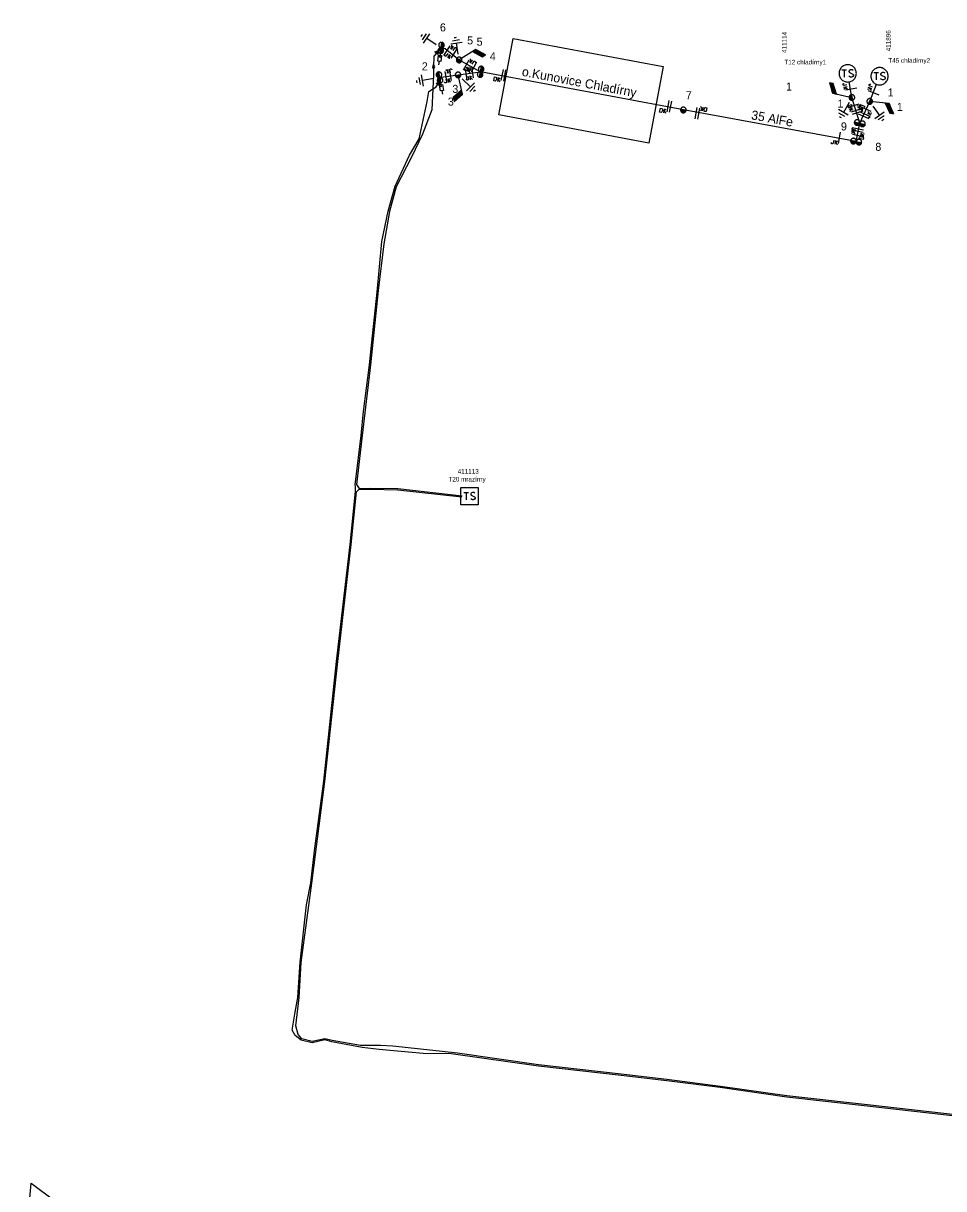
# Model space of a CAD drawing. Extents: x -540340 to -537226, y -1183949 to -1180375.
# Drawn here: x -540340 to -540138.8, y -1183666.6 to -1183411.8 of the extents above; entities that cross this region are included whole.
import ezdxf

# ---------------------------------------------------------------- set-up
doc = ezdxf.new("R2010")
doc.units = 0
for name, color, linetype in [('Default', 7, 'Continuous'), ('Vrstva 11', 7, 'Continuous'), ('Vrstva 12', 7, 'Continuous'), ('Vrstva 13', 7, 'Continuous'), ('Vrstva 14', 7, 'Continuous'), ('Vrstva 15', 7, 'Continuous'), ('Vrstva 16', 7, 'Continuous'), ('Vrstva 18', 7, 'Continuous'), ('Vrstva 19', 7, 'Continuous'), ('Vrstva 2', 7, 'Continuous'), ('Vrstva 25', 7, 'Continuous'), ('Vrstva 26', 7, 'Continuous'), ('Vrstva 27', 7, 'Continuous'), ('Vrstva 35', 7, 'Continuous'), ('Vrstva 4', 7, 'Continuous'), ('Vrstva 5', 7, 'Continuous'), ('Vrstva 52', 7, 'Continuous'), ('Vrstva 53', 7, 'Continuous'), ('Vrstva 54', 7, 'Continuous'), ('Vrstva 6', 7, 'Continuous')]:
    doc.layers.add(name, color=color, linetype=linetype)

# ---------------------------------------------------------------- blocks, each defined once
blk = doc.blocks.new('VN850')
at = {"layer": 'Vrstva 15'}
for points in [[(-0.56, 1.43), (-0.56, -1.07)], [(-0.01, 1.43), (-0.01, -1.07)], [(-2.09, -0.54), (-1.78, -0.54)], [(-2.09, -1.41), (-2.09, -0.54)], [(-1.78, -1.41), (-2.09, -1.41)], [(-1.78, -0.54), (-1.66, -0.6)], [(-1.67, -1.35), (-1.78, -1.41)], [(-1.59, -1.2), (-1.67, -1.35)], [(-1.66, -0.6), (-1.59, -0.75)], [(-1.59, -0.75), (-1.55, -0.96)], [(-1.55, -0.96), (-1.59, -1.2)], [(-1.26, -0.54), (-1.26, -1.41)], [(-0.85, -0.54), (-1.26, -1.09)], [(-1.13, -0.92), (-0.77, -1.41)]]:
    blk.add_lwpolyline(points, dxfattribs=at)
blk = doc.blocks.new('VN840')
at = {"layer": 'Vrstva 15'}
for points in [[(-0.01, 1.41), (-0.01, -1.09)], [(-1.51, -1.24), (-1.51, -1.15)], [(-1.48, -1.35), (-1.51, -1.24)], [(-1.33, -1.42), (-1.48, -1.35)], [(-1.27, -1.42), (-1.33, -1.42)], [(-1.13, -1.35), (-1.27, -1.42)], [(-1.09, -1.24), (-1.13, -1.35)], [(-1.09, -0.59), (-1.09, -1.24)], [(-0.68, -0.59), (-0.68, -1.42)], [(-0.68, -1.11), (-0.27, -0.59)], [(-0.54, -0.94), (-0.2, -1.42)]]:
    blk.add_lwpolyline(points, dxfattribs=at)
blk = doc.blocks.new('VN440')
at = {"layer": 'Vrstva 2'}
for points in [[(1.22, 0), (1.21, 0.13), (1.19, 0.25), (1.16, 0.38), (1.11, 0.5), (1.05, 0.61), (0.98, 0.72), (0.9, 0.82), (0.81, 0.91), (0.71, 0.99), (0.6, 1.06), (0.49, 1.12), (0.37, 1.16), (0.25, 1.2), (0.12, 1.22), (-0.01, 1.22), (-0.14, 1.22), (-0.26, 1.2), (-0.39, 1.16), (-0.51, 1.12), (-0.62, 1.06), (-0.73, 0.99), (-0.83, 0.91), (-0.92, 0.82), (-1, 0.72), (-1.07, 0.61), (-1.13, 0.5), (-1.18, 0.38), (-1.21, 0.25), (-1.23, 0.13), (-1.24, 0), (-1.23, -0.13), (-1.21, -0.26), (-1.18, -0.38), (-1.13, -0.5), (-1.07, -0.62), (-1, -0.73), (-0.92, -0.83), (-0.83, -0.92), (-0.73, -1), (-0.62, -1.07), (-0.51, -1.13), (-0.39, -1.17), (-0.26, -1.2), (-0.14, -1.23), (-0.01, -1.23), (0.12, -1.23), (0.25, -1.2), (0.37, -1.17), (0.49, -1.13), (0.6, -1.07), (0.71, -1), (0.81, -0.92), (0.9, -0.83), (0.98, -0.73), (1.05, -0.62), (1.11, -0.5), (1.16, -0.38), (1.19, -0.26), (1.21, -0.13), (1.22, 0)], [(-1.24, 0), (1.22, 0)], [(-1.18, -0.34), (1.1, -0.34)], [(-1.01, -0.63), (0.97, -0.63)], [(-0.74, -0.92), (0.68, -0.92)]]:
    blk.add_lwpolyline(points, dxfattribs=at)
blk = doc.blocks.new('VN870')
at = {"layer": 'Vrstva 4'}
for points in [[(0, -0.25), (0.5, 0), (0, 0.25), (-0.5, 0), (0, -0.25)], [(0.37, 0), (0, 0.19), (-0.36, 0), (0, -0.19), (0.37, 0)], [(0.24, 0), (0, 0.12), (-0.25, 0), (0, -0.12), (0.24, 0)], [(0.12, 0), (0, 0.06), (-0.13, 0), (0, -0.06), (0.12, 0)]]:
    blk.add_lwpolyline(points, dxfattribs=at)
blk = doc.blocks.new('VN890')
at = {"layer": 'Vrstva 4'}
for points in [[(-0.41, 0.41), (0.41, 0)], [(-0.41, -0.41), (-0.41, 0.41)], [(0.41, 0), (-0.41, -0.41)], [(-0.34, 0.31), (0.27, 0), (-0.34, -0.3), (-0.34, 0.31)], [(-0.26, 0.2), (0.1, 0), (-0.26, -0.18), (-0.26, 0.2)], [(-0.19, 0.09), (-0.04, 0), (-0.19, -0.08), (-0.19, 0.09)], [(-0.16, -0.01), (-0.16, 0.03), (-0.13, 0.01), (-0.16, -0.01)]]:
    blk.add_lwpolyline(points, dxfattribs=at)
blk = doc.blocks.new('VN820')
at = {"layer": 'Vrstva 13'}
for points in [[(0, 0), (0, -2.1)], [(-0.32, -1.63), (0.34, -1.63)], [(-0.32, -2.95), (-0.32, -1.63)], [(0, -2.1), (-0.12, -1.86)], [(0, -2.1), (0.12, -1.86)], [(0.34, -1.63), (0.34, -2.95)], [(0.34, -2.95), (-0.32, -2.95)], [(0, -2.95), (0, -3.75)]]:
    blk.add_lwpolyline(points, dxfattribs=at)
blk = doc.blocks.new('VN810')
at = {"layer": 'Vrstva 14'}
for points in [[(0, -1.25), (0, -3.75)], [(1.25, -3.75), (-1.25, -3.75)], [(0.77, -4.37), (-0.8, -4.37)], [(0, -5), (-0.25, -5)], [(0.27, -5), (0, -5)]]:
    blk.add_lwpolyline(points, dxfattribs=at)
blk = doc.blocks.new('VN640')
at = {"layer": 'Vrstva 6'}
for points in [[(-1.89, 1.89), (1.89, 1.89)], [(-1.89, -1.89), (-1.89, 1.89)], [(-1.26, 0.79), (-0.22, 0.79)], [(-0.73, 0.79), (-0.73, -0.79)], [(1.2, 0.66), (0.94, 0.79), (0.66, 0.79), (0.41, 0.66), (0.28, 0.47), (0.28, 0.41), (0.41, 0.22), (1.13, -0.16), (1.26, -0.32), (1.26, -0.47), (1.13, -0.66), (0.91, -0.79), (0.63, -0.79), (0.5, -0.73), (0.28, -0.6)], [(1.89, 1.89), (1.89, -1.89)], [(1.89, -1.89), (-1.89, -1.89)]]:
    blk.add_lwpolyline(points, dxfattribs=at)
blk = doc.blocks.new('VN610')
at = {"layer": 'Vrstva 6'}
for points in [[(1.88, 0), (1.87, 0.2), (1.84, 0.39), (1.79, 0.58), (1.72, 0.77), (1.63, 0.94), (1.52, 1.11), (1.4, 1.26), (1.26, 1.4), (1.1, 1.53), (0.94, 1.63), (0.76, 1.72), (0.58, 1.8), (0.39, 1.85), (0.19, 1.88), (-0.01, 1.89), (-0.21, 1.88), (-0.4, 1.85), (-0.59, 1.8), (-0.78, 1.72), (-0.95, 1.63), (-1.12, 1.53), (-1.27, 1.4), (-1.41, 1.26), (-1.54, 1.11), (-1.64, 0.94), (-1.73, 0.77), (-1.8, 0.58), (-1.86, 0.39), (-1.89, 0.2), (-1.9, 0), (-1.89, -0.2), (-1.86, -0.39), (-1.8, -0.58), (-1.73, -0.77), (-1.64, -0.95), (-1.54, -1.11), (-1.41, -1.27), (-1.27, -1.41), (-1.12, -1.53), (-0.95, -1.64), (-0.78, -1.73), (-0.59, -1.8), (-0.4, -1.85), (-0.21, -1.88), (-0.01, -1.89), (0.19, -1.88), (0.39, -1.85), (0.58, -1.8), (0.76, -1.73), (0.94, -1.64), (1.1, -1.53), (1.26, -1.41), (1.4, -1.27), (1.52, -1.11), (1.63, -0.95), (1.72, -0.77), (1.79, -0.58), (1.84, -0.39), (1.87, -0.2), (1.88, 0)], [(-1.27, 0.78), (-0.26, 0.78)], [(-0.76, 0.78), (-0.76, -0.79)], [(1.19, 0.66), (0.94, 0.78), (0.62, 0.78), (0.37, 0.66), (0.24, 0.47), (0.24, 0.4), (0.37, 0.22), (1.12, -0.16), (1.25, -0.32), (1.25, -0.48), (1.12, -0.67), (0.87, -0.79), (0.62, -0.79), (0.49, -0.73), (0.24, -0.6)]]:
    blk.add_lwpolyline(points, dxfattribs=at)
blk = doc.blocks.new('VN450')
at = {"layer": 'Vrstva 2'}
for points in [[(0, 0), (-0.01, 0.13), (-0.03, 0.25), (-0.06, 0.38), (-0.11, 0.5), (-0.16, 0.61), (-0.23, 0.72), (-0.31, 0.82), (-0.4, 0.91), (-0.5, 0.99), (-0.61, 1.06), (-0.72, 1.11), (-0.84, 1.16), (-0.97, 1.19), (-1.09, 1.21), (-1.22, 1.22), (-1.35, 1.21), (-1.47, 1.19), (-1.59, 1.16), (-1.71, 1.11), (-1.83, 1.06), (-1.93, 0.99), (-2.03, 0.91), (-2.12, 0.82), (-2.2, 0.72), (-2.27, 0.61), (-2.33, 0.5), (-2.38, 0.38), (-2.41, 0.25), (-2.43, 0.13), (-2.44, 0), (-2.43, -0.13), (-2.41, -0.25), (-2.38, -0.38), (-2.33, -0.5), (-2.27, -0.61), (-2.2, -0.72), (-2.12, -0.82), (-2.03, -0.91), (-1.93, -0.99), (-1.83, -1.06), (-1.71, -1.11), (-1.59, -1.16), (-1.47, -1.19), (-1.35, -1.21), (-1.22, -1.22), (-1.09, -1.21), (-0.97, -1.19), (-0.84, -1.16), (-0.72, -1.11), (-0.61, -1.06), (-0.5, -0.99), (-0.4, -0.91), (-0.31, -0.82), (-0.23, -0.72), (-0.16, -0.61), (-0.11, -0.5), (-0.06, -0.38), (-0.03, -0.25), (-0.01, -0.13), (0, 0)], [(-2.44, 0), (2.44, 0)], [(2.44, 0), (2.43, 0.13), (2.41, 0.25), (2.38, 0.38), (2.33, 0.5), (2.27, 0.61), (2.2, 0.72), (2.12, 0.82), (2.03, 0.91), (1.94, 0.99), (1.83, 1.06), (1.71, 1.11), (1.6, 1.16), (1.47, 1.19), (1.35, 1.21), (1.22, 1.22), (1.09, 1.21), (0.97, 1.19), (0.84, 1.16), (0.72, 1.11), (0.61, 1.06), (0.5, 0.99), (0.4, 0.91), (0.31, 0.82), (0.23, 0.72), (0.16, 0.61), (0.11, 0.5), (0.06, 0.38), (0.03, 0.25), (0.01, 0.13), (0, 0), (0.01, -0.13), (0.03, -0.25), (0.06, -0.38), (0.11, -0.5), (0.16, -0.61), (0.23, -0.72), (0.31, -0.82), (0.4, -0.91), (0.5, -0.99), (0.61, -1.06), (0.72, -1.11), (0.84, -1.16), (0.97, -1.19), (1.09, -1.21), (1.22, -1.22), (1.35, -1.21), (1.47, -1.19), (1.6, -1.16), (1.71, -1.11), (1.83, -1.06), (1.94, -0.99), (2.03, -0.91), (2.12, -0.82), (2.2, -0.72), (2.27, -0.61), (2.33, -0.5), (2.38, -0.38), (2.41, -0.25), (2.43, -0.13), (2.44, 0)], [(-2.4, -0.31), (-0.04, -0.31)], [(-2.26, -0.61), (-0.17, -0.61)], [(-2.01, -0.92), (-0.42, -0.92)], [(0.04, -0.31), (2.4, -0.31)], [(0.17, -0.61), (2.27, -0.61)], [(0.42, -0.92), (2.02, -0.92)]]:
    blk.add_lwpolyline(points, dxfattribs=at)
blk = doc.blocks.new('VN001')
at = {"layer": 'Default'}
for p, q in [((1.73, 3.03), (4.14, 3.03)), ((1.76, 3.08), (4.17, 3.08)), ((1.79, 3.13), (4.2, 3.13)), ((1.82, 3.18), (4.23, 3.18)), ((1.85, 3.23), (4.26, 3.23)), ((1.87, 3.28), (4.29, 3.28)), ((1.9, 3.33), (4.32, 3.33)), ((1.93, 3.38), (4.35, 3.38)), ((1.96, 3.43), (4.37, 3.43)), ((1.99, 3.48), (4.4, 3.48)), ((2.02, 3.53), (4.43, 3.53)), ((2.05, 3.58), (4.46, 3.58)), ((2.07, 3.63), (4.49, 3.63)), ((2.1, 3.68), (4.52, 3.68)), ((2.13, 3.73), (2.54, 3.73))]:
    blk.add_line(p, q, dxfattribs=at)
blk.add_lwpolyline([(2.13, 3.73), (0, 0)], dxfattribs=at)
blk.add_lwpolyline([(4.55, 3.73), (2.13, 3.73), (1.7, 2.98), (4.12, 2.99)], close=True, dxfattribs=at)

msp = doc.modelspace()

# ---------------------------------------------------------------- linework, layer by layer
at = {"layer": 'Vrstva 35'}
for points in [[(-540232.9, -1183415.07), (-540200.11, -1183421.24), (-540203.26, -1183437.95), (-540236.04, -1183431.77)], [(-540099.18, -1183843.5), (-540075.2, -1183846.48), (-540065.47, -1183765.95), (-540052.99, -1183646.29), (-540036.08, -1183648.06), (-540048.58, -1183767.85), (-540059.33, -1183856.85), (-540059.45, -1183876.18), (-540076.45, -1183876.06), (-540087.82, -1183869.73), (-540106.08, -1183859.73), (-540163.52, -1183816.9), (-540239.44, -1183760.31), (-540323.17, -1183697.88), (-540340.03, -1183685.32), (-540338.32, -1183665.38), (-540313.01, -1183684.25), (-540229.28, -1183746.68), (-540153.36, -1183803.27)]]:
    msp.add_lwpolyline(points, close=True, dxfattribs=at)
at = {"layer": 'Vrstva 4'}
for points in [[(-540158.86, -1183428), (-540159.45, -1183424.58)], [(-540154.96, -1183428.84), (-540153.49, -1183425.08)], [(-540157.13, -1183433.61), (-540158.86, -1183428)], [(-540157.13, -1183433.61), (-540154.96, -1183428.84)], [(-540157.93, -1183437.63), (-540157.13, -1183433.61)]]:
    msp.add_lwpolyline(points, dxfattribs=at)
at = {"layer": 'Vrstva 5'}
for points in [[(-540248.69, -1183417.14), (-540250.29, -1183418.96), (-540250.31, -1183421.31)], [(-540250.31, -1183421.31), (-540250.32, -1183423.04), (-540250.63, -1183429.18), (-540250.71, -1183430.71), (-540252.75, -1183436), (-540255.17, -1183441.06), (-540258.47, -1183447.51), (-540259.99, -1183452.91), (-540261.21, -1183460), (-540262.41, -1183470.18), (-540264.1, -1183486.46), (-540265.94, -1183501.93), (-540267.2, -1183512.64), (-540266.56, -1183513.47), (-540264.04, -1183513.41), (-540258.11, -1183513.52), (-540244.1, -1183515.07)], [(-540118.9, -1183652.68), (-540155.51, -1183648.54), (-540173.09, -1183646.55), (-540187.65, -1183644.47), (-540199.33, -1183642.99), (-540209.34, -1183641.83), (-540227.38, -1183639.78), (-540246.47, -1183637.1), (-540252.6, -1183637.04), (-540262.24, -1183636.13), (-540265.93, -1183635.71), (-540272.54, -1183634.47), (-540274.12, -1183634.07), (-540276.85, -1183634.67), (-540279.24, -1183634.08), (-540280.62, -1183633.07), (-540281.24, -1183631.92), (-540280.59, -1183627.99), (-540279.97, -1183624.8), (-540279.52, -1183617.09), (-540278.08, -1183604.54), (-540277.19, -1183599.74), (-540276.36, -1183592.74), (-540274.32, -1183577.51), (-540271.54, -1183551.28), (-540268.57, -1183525.7), (-540267.39, -1183514.12), (-540267.38, -1183513.03), (-540267.46, -1183512.71), (-540266.19, -1183501.9), (-540265.64, -1183496.65), (-540264.34, -1183486.43), (-540263.84, -1183481.48), (-540262.68, -1183470.56), (-540261.66, -1183459.47), (-540260.23, -1183452.85), (-540258.7, -1183447.41), (-540255.58, -1183440.58), (-540253.5, -1183437.02), (-540251.7, -1183428.85), (-540251.34, -1183426.69), (-540249.73, -1183425.64), (-540248.73, -1183424.07), (-540248.74, -1183423.66), (-540249.03, -1183423.61)], [(-540118.87, -1183652.43), (-540155.48, -1183648.29), (-540173.06, -1183646.3), (-540187.61, -1183644.22), (-540199.3, -1183642.74), (-540209.31, -1183641.58), (-540227.35, -1183639.53), (-540245.11, -1183636.98), (-540259.22, -1183635.45), (-540261.96, -1183635.31), (-540266.33, -1183635.25), (-540272.49, -1183634.22), (-540274.11, -1183633.81), (-540276.85, -1183634.41), (-540279.11, -1183633.85), (-540279.95, -1183632.91), (-540280.42, -1183630.98), (-540279.72, -1183624.82), (-540279.27, -1183617.12), (-540276.95, -1183599.78), (-540274.07, -1183577.54), (-540271.29, -1183551.3), (-540268.32, -1183525.73), (-540267.15, -1183514.23), (-540266.69, -1183513.72), (-540264.04, -1183513.66), (-540258.12, -1183513.77), (-540244.13, -1183515.31)]]:
    msp.add_lwpolyline(points, dxfattribs=at)
at = {"layer": 'Vrstva 52'}
for points in [[(-540248.69, -1183417.14), (-540247.79, -1183417.27), (-540244.72, -1183419.78)], [(-540244.72, -1183419.77), (-540240.04, -1183422.37)], [(-540249.03, -1183423.61), (-540248.15, -1183423.44), (-540244.97, -1183423.04)], [(-540244.97, -1183423.04), (-540240.04, -1183422.37)], [(-540195.7, -1183430.72), (-540240.04, -1183422.37)], [(-540157.93, -1183437.63), (-540195.7, -1183430.72)]]:
    msp.add_lwpolyline(points, dxfattribs=at)

# ---------------------------------------------------------------- block references
at = {"layer": 'Vrstva 11'}
for p, rotation in [((-540244.72, -1183419.77), -28.299599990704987), ((-540244.97, -1183423.04), -137.72051106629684), ((-540158.86, -1183428), 107.19590279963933), ((-540154.97, -1183428.84), -66.57340553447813)]:
    msp.add_blockref('VN001', p, dxfattribs=dict(at, rotation=rotation))
at = {"layer": 'Vrstva 13'}
for name, p, xscale, yscale, rotation in [('VN450', (-540248.68, -1183417.14), 0.5, 0.5, 81.8771138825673), ('VN440', (-540244.72, -1183419.78), 0.5, 0.5, -28.316347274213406), ('VN450', (-540240.04, -1183422.37), 0.5000000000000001, 0.5, 79.52871113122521), ('VN450', (-540249.03, -1183423.61), 0.5, 0.5, -78.54001944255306), ('VN440', (-540244.97, -1183423.04), 0.49999999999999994, 0.5000000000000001, 10.003794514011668), ('VN440', (-540158.86, -1183428), 0.5, 0.5, -72.44218613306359), ('VN440', (-540154.96, -1183428.84), 0.49999999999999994, 0.5, 65.62446113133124), ('VN440', (-540195.7, -1183430.72), 0.49999999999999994, 0.49999999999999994, -11.620397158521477), ('VN450', (-540157.13, -1183433.61), 0.5, 0.5, -14.150816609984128), ('VN450', (-540157.93, -1183437.63), 0.5, 0.5, -10.367486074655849)]:
    msp.add_blockref(name, p, dxfattribs=dict(at, xscale=xscale, yscale=yscale, rotation=rotation))
at = {"layer": 'Vrstva 15'}
for p, rotation in [((-540248.69, -1183417.15), -123.28151660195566), ((-540244.72, -1183419.77), -170.71573883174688), ((-540249.03, -1183423.61), -79.8778555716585), ((-540244.97, -1183423.04), 45.79327784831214), ((-540158.86, -1183428), -29.87806100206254), ((-540154.96, -1183428.84), 34.77296112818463)]:
    msp.add_blockref('VN810', p, dxfattribs=dict(at, rotation=rotation))
at = {"layer": 'Vrstva 16'}
for p, rotation in [((-540248.69, -1183417.14), -8.012644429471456), ((-540249.03, -1183423.61), 10.543247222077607)]:
    msp.add_blockref('VN820', p, dxfattribs=dict(at, rotation=rotation))
at = {"layer": 'Vrstva 18'}
for name, p, rotation in [('VN840', (-540247.3, -1183417.59), 146.9457833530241), ('VN840', (-540245.95, -1183418.47), -33.05421664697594), ('VN840', (-540247.6, -1183423.35), -170.17123335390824), ('VN840', (-540243.1, -1183420.67), 151.01294718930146), ('VN840', (-540241.58, -1183421.52), -28.98705281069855), ('VN840', (-540241.81, -1183422.61), 7.7573916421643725), ('VN840', (-540243.21, -1183422.8), -172.242608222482), ('VN850', (-540234.86, -1183423.35), -10.67036096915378), ('VN840', (-540246.64, -1183423.18), 9.828766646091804), ('VN840', (-540159.17, -1183426.23), -80.23665277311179), ('VN840', (-540154.22, -1183426.94), -111.41374716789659), ('VN850', (-540198.58, -1183430.18), -10.670361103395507), ('VN850', (-540157.81, -1183431.39), -72.79968324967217), ('VN840', (-540158.34, -1183429.71), 107.20031668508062), ('VN850', (-540192.87, -1183431.24), 169.631886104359), ('VN850', (-540156.42, -1183432.06), -114.37335558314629), ('VN840', (-540155.74, -1183430.55), 65.62664441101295), ('VN840', (-540161.66, -1183436.95), -10.368113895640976), ('VN850', (-540157.37, -1183434.82), 78.65170828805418), ('VN840', (-540157.67, -1183436.32), -101.34829171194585)]:
    msp.add_blockref(name, p, dxfattribs=dict(at, rotation=rotation))
at = {"layer": 'Vrstva 19'}
for name, p, rotation in [('VN890', (-540249.44, -1183418), 48.45101103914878), ('VN870', (-540250.31, -1183421.31), 89.55106940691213), ('VN890', (-540249.18, -1183424.77), 57.50519991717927)]:
    msp.add_blockref(name, p, dxfattribs=dict(at, rotation=rotation))
at = {"layer": 'Vrstva 25'}
for name, p in [('VN610', (-540159.77, -1183422.72)), ('VN610', (-540152.81, -1183423.34)), ('VN640', (-540242.48, -1183515.15))]:
    msp.add_blockref(name, p, dxfattribs=at)

# ---------------------------------------------------------------- texts
at = {"layer": 'Vrstva 12'}
for s, p in [('5', (-540240.91, -1183416.66)), ('1', (-540173.26, -1183426.47)), ('3', (-540247.2, -1183429.76)), ('1', (-540149.04, -1183430.91))]:
    msp.add_text(s, height=1.75, dxfattribs=at).set_placement(p)
at = {"layer": 'Vrstva 14'}
for s, p in [('6', (-540248.94, -1183413.54)), ('5', (-540242.99, -1183416.38)), ('4', (-540238.02, -1183419.83)), ('2', (-540252.89, -1183422.06)), ('3', (-540246.22, -1183426.98)), ('7', (-540195.17, -1183428.36)), ('1', (-540151.04, -1183427.77)), ('1', (-540162.01, -1183430.22)), ('9', (-540161.26, -1183435.19)), ('8', (-540153.73, -1183439.65))]:
    msp.add_text(s, height=1.75, dxfattribs=at).set_placement(p)
at = {"layer": 'Vrstva 26'}
for s, p in [('411114', (-540173.12, -1183418.25)), ('411896', (-540150.39, -1183417.89))]:
    msp.add_text(s, height=1, rotation=90, dxfattribs=at).set_placement(p)
msp.add_text('411113', height=1, dxfattribs=at).set_placement((-540245.05, -1183510.24))
at = {"layer": 'Vrstva 27'}
for s, p in [('T12 chladírny1', (-540173.62, -1183420.75)), ('T45 chladírny2', (-540150.89, -1183420.39)), ('T20 mrazírny', (-540247.07, -1183511.96))]:
    msp.add_text(s, height=1, dxfattribs=at).set_placement(p)
at = {"layer": 'Vrstva 53'}
msp.add_text('35 AlFe', height=2, rotation=349.632, dxfattribs=at).set_placement((-540181, -1183432.73))
at = {"layer": 'Vrstva 54'}
msp.add_text('o.Kunovice Chladírny', height=2, rotation=349.33, dxfattribs=at).set_placement((-540231.13, -1183423.23))

doc.saveas('drawing.dxf')
